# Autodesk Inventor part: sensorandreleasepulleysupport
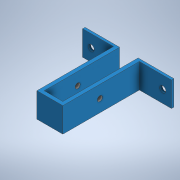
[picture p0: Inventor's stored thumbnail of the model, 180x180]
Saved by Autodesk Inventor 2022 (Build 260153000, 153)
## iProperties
Created: 2021-06
Part Number: sensorandreleasepulleysupport
Material: Generic
Document SubType Name: Modeling
Designer: Chimms
Density: 1 g/cm^3
Appearance: Default
Author: Chimms
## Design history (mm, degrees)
sketch "Sketch1"
  geometry: L1 (0, 0)-(-25, 0); L2 (-25, 0)-(-25, 20); L3 (-25, 20)-(0, 20); L4 (0, 20)-(0, 0); L5 (0, 20)-(7, 20); L6 (7, 20)-(7, 0); L7 (7, 0)-(0, 0); L8 (0, 0)-(0, 20)
  constraints: 16 end point, 4 parallel, 2 horizontal, 2 perpendicular
  dimensions: "d0" = 25 distance of L2.end L3.end; "d1" = 20 distance of L1.end L2.end; "d2" = 7 distance of L6.end L7.end
extrude "Extrusion1" new body sketch "Sketch1" distance "d3" = 2; taper "d4" = 0 deg
sketch "Sketch2"
  geometry: L1 (0, 0)-(0, 20) reference; L2 (0, 20)-(-3, 20); L3 (-3, 20)-(-3, 0); L4 (-3, 0)-(0, 0); L5 (0, 0)-(0, 20); 1 further point
  constraints: 8 end point, 2 parallel, 1 horizontal, 1 perpendicular
  dimensions: "d5" = 3 distance of L4.end L3.end
extrude "Extrusion2" join sketch "Sketch2" distance "d6" = 64; taper "d7" = 0 deg
sketch "Sketch3"
  geometry: L1 (-2, 20)-(-64, 20) reference; L2 (-2, 0)-(-64, 0) reference; L3 (-64, 20)-(-61, 20); L4 (-61, 20)-(-61, 0); L5 (-61, 0)-(-64, 0); L6 (-64, 0)-(-64, 20); 3 further points
  constraints: 8 end point, 2 parallel, 1 horizontal, 1 perpendicular, 1 point on line
  dimensions: "d8" = 3 distance of L4.end L5.end
extrude "Extrusion3" join sketch "Sketch3" distance "d9" = 18; taper "d10" = 0 deg
sketch "Sketch4"
  geometry: L1 (0, 20)-(-18, 20) reference; L2 (0, 0)-(-18, 0) reference; L3 (-18, 20)-(-15, 20); L4 (-15, 20)-(-15, 0); L5 (-15, 0)-(-18, 0); L6 (-18, 0)-(-18, 20); 3 further points
  constraints: 8 end point, 2 parallel, 1 horizontal, 1 perpendicular, 1 point on line
  dimensions: "d11" = 3 distance of L4.end L5.end
extrude "Extrusion4" join sketch "Sketch4" distance "d12" = 59; taper "d13" = 0 deg
sketch "Sketch5"
  geometry: L1 (-64, 20)-(-2, 20) reference; L2 (-2, 20)-(0, 20); L3 (0, 20)-(0, 0); L4 (0, 0)-(-2, 0); L5 (-2, 0)-(-2, 20)
  constraints: 8 end point, 2 parallel, 1 horizontal, 1 perpendicular
extrude "Extrusion5" join sketch "Sketch5" distance "d14" = 3; taper "d15" = 0 deg
sketch "Sketch6"
  geometry: L1 (0, 20)-(-61, 20) reference; L2 (-2, 0)-(-64, 0) reference; L3 (0, 20)-(-2, 20); L4 (-2, 20)-(-2, 0); L5 (-2, 0)-(0, 0); L6 (0, 0)-(0, 20); 2 further points
  constraints: 8 end point, 2 parallel, 1 horizontal, 1 perpendicular
extrude "Extrusion6" join sketch "Sketch6" distance "d16" = 26; taper "d17" = 0 deg
sketch "Sketch7"
  geometry: L1 (-25, 20)-(-25, 0) reference; L2 (47, 0)-(47, 20) reference; C1 r 2.5 at (-18, 10); C2 r 2.5 at (40, 10); 1 further point
  constraints: 2 centre point
  dimensions: "d19" = 5 diameter of C1; "d21" = 5 diameter of C2
extrude "Extrusion7" cut sketch "Sketch7" extent not by distance; stored distance "d22" = 0; taper "d23" = 0 deg
sketch "Sketch8"
  geometry: 1 further point
sketch "Sketch9"
  geometry: L1 (-64, 20)-(-64, 0) reference; L2 (-64, 10)-(-44, 10); L3 (-44, 10)-(-34, 10); C1 r 2 at (-34, 10); 1 further point
  constraints: 4 end point, 2 horizontal, 1 centre point, 1 coincident, 1 midpoint
  dimensions: "d24" = 20 distance of L2.start L2.end; "d25" = 10 distance of L2.end L3.end; "d26" = 4 diameter of C1
extrude "Extrusion8" cut sketch "Sketch9" extent not by distance; stored distance "d27" = 0; taper "d28" = 0 deg
body "Solid1"
